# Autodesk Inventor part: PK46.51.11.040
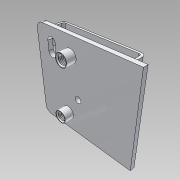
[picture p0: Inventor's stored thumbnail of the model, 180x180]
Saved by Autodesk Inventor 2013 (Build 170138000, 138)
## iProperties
Created: 2012-10
Part Number: PK46.51.11.040
Material: Aluminum 6061
Document SubType Name: Modeling
Designer: VMuser
Density: 2.71 g/cm^3
Mass: 96.308 g
Surface Area: 239.3 cm^2
Volume: 35.538 cm^3
Author: VMuser
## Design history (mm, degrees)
derived "PK46.51.11.040.iam"
body "Solid1"
node "ПК46.51.11.041:1"
node "PK46.51.11.044.ipt:1"
node "PK46.51.11.044.ipt:2"
node "PK46.51.11.042.ipt:1"
node "PK46.51.11.042.ipt:2"
node "PK46.51.11.040.iam_Bodies"
